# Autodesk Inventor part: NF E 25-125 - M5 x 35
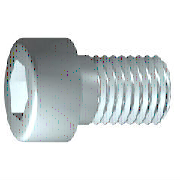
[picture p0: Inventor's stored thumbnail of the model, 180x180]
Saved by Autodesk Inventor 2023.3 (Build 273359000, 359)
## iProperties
IsCustomPart: 0
Created: 2022-02
Part Number: NF E 25-125 - M5 x 35
Material: Acier, doux
Description: Tête cylindrique fendue - Produit de classe A - Symbole C S
Document SubType Name: Modeling
Standard: NF E 25-125
Designer: Thier
Standards Organization: AFNOR
Language: fr-FR
Size Designation: M5 x 35
Categories: <MemberInstance><Categories><Category DisplayName="Visserie" InternalName="e4da775c-781d-43d5-af7c-5136215cf5a6" Mnemonic="FSTN"><Category DisplayName="Vis" Int
Density: 7.85 g/cm^3
Appearance: Semi-poli
Author: Thier
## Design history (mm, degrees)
sketch "Esquisse1"
  geometry: L1 (-1.167, 0)-(35, 0); L2 (35, 0)-(35, 2.5); L3 (35, 2.5)-(13, 2.5); L4 (13, 2.5)-(12.509, 2.5); L5 (12.509, 2.5)-(0, 2.5); L6 (0, 2.5)-(0, 4.25); L7 (0, 4.25)-(-5, 4.25); L8 (-5, 4.25)-(-5, 2.309); L9 (-5, 2.309)-(-2.5, 2.309); L10 (-2.5, 2.309)-(-1.167, 0); L11 (-13, 0)-(43, 0) reference; L12 (0, -0.85)-(0, 5.1) reference; L13 (13, 2.5)-(0, 2.5)
  constraints: 22 end point, 6 parallel, 2 collinear, 2 perpendicular, 1 horizontal, 1 point on line
  dimensions: "d1" = 22 distance from line of L3.end L2 (= GEL); "d2" = 0.49086 distance of L4.end L3.end (computed from GAL); "d3" = 5 distance between parallel lines of L8 L6 (= KOH); "d4" = 2.5 distance of L8.end L9.end (= INTI); "d5" = 60 deg angle of L10 L1; "d6" = 5 diameter of L3 L1 (= GD); "d7" = 5 diameter of L5 L1 (= BDM); "d8" = 4.6188 diameter of L9 L1 (= 1.1547 x SW); "d9" = 8.5 diameter of L7 L1 (= KOD); "d26" = 35 distance between parallel lines of L12 L2 (= NLG)
revolve "Corps" sketch "Esquisse1" stored, may be unused: angle "d10" = 90 deg
sketch "Esquisse2"
  geometry: L1 (0, -5.95)-(0, 5.95) reference; L2 (-5.95, 0)-(5.95, 0) reference; L3 (2.309, 0)-(1.155, -2); L4 (1.155, -2)-(-1.155, -2); L5 (-1.155, -2)-(-2.309, 0); L6 (-2.309, 0)-(-1.155, 2); L7 (-1.155, 2)-(1.155, 2); L8 (1.155, 2)-(2.309, 0); 2 further points
  constraints: 12 end point, 1 coincident, 1 horizontal alignment, 1 point on line, 12 other
extrude "Rainure" join sketch "Esquisse2" stored distance "d11" = 10; taper "d12" = 0 deg
workplane "Work Plane1"
fillet "Fillet2" dims "d30" = 0.1 (= R)
body "Solid1"
fillet "Congé1" dims "d17" = 0.5 (= RR)
feature "Filetage" dims "d13" = 22 (= GEL), "d14" = 0
chamfer "Chanfrein1" distance "d15" = 0.49076 (= -0.5 x SPD + 0.5 x GD); stored, may be unused: second distance "d16" = 0.49076 (= GUL), angle "d27" = 45 deg
other parameters: "GD" = 5 (= NND) [user parameter; used in 2 equation terms], "NLG" = 35 [user parameter; used in 1 equation term], "GEL" = 22 [user parameter; used in 2 equation terms], "KOD" = 8.5 [user parameter; used in 1 equation term], "KOH" = 5 (= NND) [user parameter; used in 1 equation term], "INTI" = 2.5 [user parameter; used in 1 equation term], "GAL" = 0.49076 (= 0.61345 x PTC) [user parameter; used in 1 equation term], "GUL" = 0.49076 (= 0.61345 x PTC) [user parameter; used in 1 equation term], "BDM" = 5 (= NND) [user parameter; used in 1 equation term], "SW" = 4 [user parameter; used in 2 equation terms], "RR" = 0.5 [user parameter; used in 1 equation term], "SPD" = 4.01848 (= NND - 1.2269 x PTC) [user parameter; used in 1 equation term], "d19" = 0, "d28" = 0, "d29" = 0, "R" = 0.1 [user parameter; used in 1 equation term], "TOA" = 30 deg [user parameter], "GD1" = 4.01848 (= THREADDIA - 1.2269 x PTC) [user parameter], "THREADDIA" = 5 [user parameter; used in 1 equation term], "FAWI" = 45 deg [user parameter], "TPU" = 12.5 (computed from PTC) [user parameter], "PTC" = 0.8 [user parameter; used in 5 equation terms], "NND" = 5 [user parameter; used in 4 equation terms], "E0" = 4.62 (= 1.155 x SW) [user parameter]
